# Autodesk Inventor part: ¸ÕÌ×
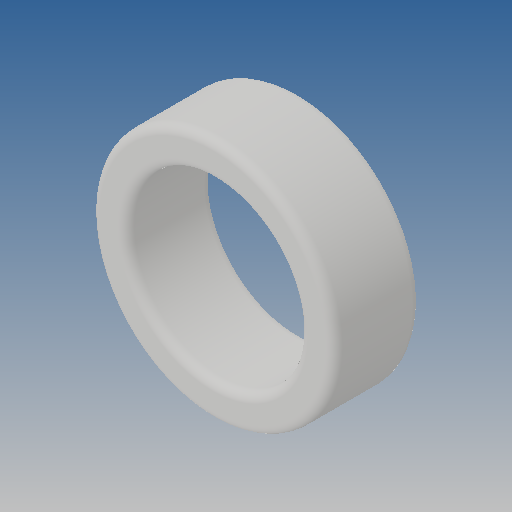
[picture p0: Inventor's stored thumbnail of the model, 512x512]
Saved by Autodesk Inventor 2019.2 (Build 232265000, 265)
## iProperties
Created: 2013-07
Part Number: ¸ÕÌ×
Material: Ogólny
Document SubType Name: Modeling
Designer: CADENGINEERING4
Density: 1 g/cm^3
Appearance: Domyślna
Author: CADENGINEERING4
Revision Number: ÈÎºÎ
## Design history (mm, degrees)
feature "Ô²½Ç3"
node "Bryła1"
